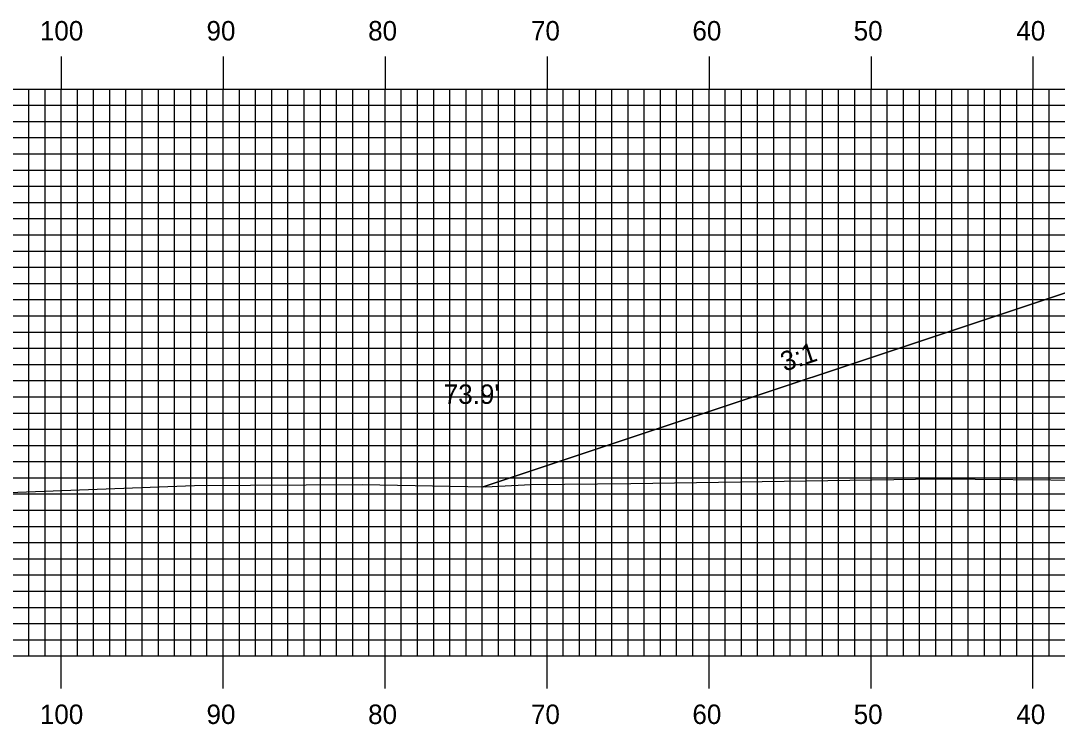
# Model space of a CAD drawing. Extents: x 1788943 to 1789287, y 442591 to 442811.
# Drawn here: x 1789006.7 to 1789070.7, y 442659.4 to 442702.9 of the extents above; entities that cross this region are included whole.
import ezdxf

# ---------------------------------------------------------------- set-up
doc = ezdxf.new("R2010")
doc.units = 0
for name, color, linetype in [('ANNOTATION', 7, 'Continuous'), ('D_Roadway_Centerline', 7, 'Continuous'), ('D_Roadway_SlopeLines', 7, 'Continuous'), ('D_Text_Standard', 7, 'Continuous'), ('H_V ANNOTATION', 7, 'Continuous'), ('MAJOR', 7, 'Continuous'), ('MINOR', 7, 'Continuous'), ('S_Roadway_Centerline', 7, 'Continuous')]:
    doc.layers.add(name, color=color, linetype=linetype)

msp = doc.modelspace()

# ---------------------------------------------------------------- linework, layer by layer
at = {"layer": 'D_Roadway_Centerline'}
msp.add_lwpolyline([(1789035.212, 442674.103), (1789075.728, 442687.608), (1789079.49, 442688.548), (1789087.728, 442690.608), (1789097.156, 442690.985), (1789109.156, 442691.249), (1789121.156, 442691.513), (1789137.57, 442690.857), (1789145.201, 442688.949), (1789149.57, 442687.857), (1789185.572, 442675.856)], dxfattribs=at)
at = {"layer": 'D_Roadway_SlopeLines'}
msp.add_lwpolyline([(1789087.728, 442690.608), (1789075.728, 442687.608), (1789035.212, 442674.103)], dxfattribs=at)
at = {"layer": 'MAJOR'}
for p, q in [((1789009.156, 442700.669), (1789009.156, 442698.665)), ((1789019.156, 442700.669), (1789019.156, 442698.665)), ((1789029.156, 442700.669), (1789029.156, 442698.665)), ((1789039.156, 442700.669), (1789039.156, 442698.665)), ((1789049.156, 442700.669), (1789049.156, 442698.665)), ((1789059.156, 442700.669), (1789059.156, 442698.665)), ((1789069.156, 442700.669), (1789069.156, 442698.665)), ((1788969.156, 442698.665), (1789249.156, 442698.665)), ((1788969.156, 442698.665), (1789249.156, 442698.665)), ((1789009.156, 442663.665), (1789009.156, 442698.665)), ((1789019.156, 442663.665), (1789019.156, 442698.665)), ((1789029.156, 442663.665), (1789029.156, 442698.665)), ((1789039.156, 442663.665), (1789039.156, 442698.665)), ((1789049.156, 442663.665), (1789049.156, 442698.665)), ((1789059.156, 442663.665), (1789059.156, 442698.665)), ((1789069.156, 442663.665), (1789069.156, 442698.665)), ((1788969.156, 442693.665), (1789249.156, 442693.665)), ((1788969.156, 442688.665), (1789249.156, 442688.665)), ((1788969.156, 442683.665), (1789249.156, 442683.665)), ((1788969.156, 442678.665), (1789249.156, 442678.665)), ((1788969.156, 442673.665), (1789249.156, 442673.665)), ((1788969.156, 442668.665), (1789249.156, 442668.665)), ((1788969.156, 442663.665), (1789249.156, 442663.665)), ((1788969.156, 442663.665), (1789249.156, 442663.665)), ((1789009.156, 442661.661), (1789009.156, 442663.665)), ((1789019.156, 442661.661), (1789019.156, 442663.665)), ((1789029.156, 442661.661), (1789029.156, 442663.665)), ((1789039.156, 442661.661), (1789039.156, 442663.665)), ((1789049.156, 442661.661), (1789049.156, 442663.665)), ((1789059.156, 442661.661), (1789059.156, 442663.665)), ((1789069.156, 442661.661), (1789069.156, 442663.665))]:
    msp.add_line(p, q, dxfattribs=at)
at = {"layer": 'MINOR'}
for p, q in [((1789007.156, 442663.665), (1789007.156, 442698.665)), ((1789008.156, 442663.665), (1789008.156, 442698.665)), ((1789010.156, 442663.665), (1789010.156, 442698.665)), ((1789011.156, 442663.665), (1789011.156, 442698.665)), ((1789012.156, 442663.665), (1789012.156, 442698.665)), ((1789013.156, 442663.665), (1789013.156, 442698.665)), ((1789014.156, 442663.665), (1789014.156, 442698.665)), ((1789015.156, 442663.665), (1789015.156, 442698.665)), ((1789016.156, 442663.665), (1789016.156, 442698.665)), ((1789017.156, 442663.665), (1789017.156, 442698.665)), ((1789018.156, 442663.665), (1789018.156, 442698.665)), ((1789020.156, 442663.665), (1789020.156, 442698.665)), ((1789021.156, 442663.665), (1789021.156, 442698.665)), ((1789022.156, 442663.665), (1789022.156, 442698.665)), ((1789023.156, 442663.665), (1789023.156, 442698.665)), ((1789024.156, 442663.665), (1789024.156, 442698.665)), ((1789025.156, 442663.665), (1789025.156, 442698.665)), ((1789026.156, 442663.665), (1789026.156, 442698.665)), ((1789027.156, 442663.665), (1789027.156, 442698.665)), ((1789028.156, 442663.665), (1789028.156, 442698.665)), ((1789030.156, 442663.665), (1789030.156, 442698.665)), ((1789031.156, 442663.665), (1789031.156, 442698.665)), ((1789032.156, 442663.665), (1789032.156, 442698.665)), ((1789033.156, 442663.665), (1789033.156, 442698.665)), ((1789034.156, 442663.665), (1789034.156, 442698.665)), ((1789035.156, 442663.665), (1789035.156, 442698.665)), ((1789036.156, 442663.665), (1789036.156, 442698.665)), ((1789037.156, 442663.665), (1789037.156, 442698.665)), ((1789038.156, 442663.665), (1789038.156, 442698.665)), ((1789040.156, 442663.665), (1789040.156, 442698.665)), ((1789041.156, 442663.665), (1789041.156, 442698.665)), ((1789042.156, 442663.665), (1789042.156, 442698.665)), ((1789043.156, 442663.665), (1789043.156, 442698.665)), ((1789044.156, 442663.665), (1789044.156, 442698.665)), ((1789045.156, 442663.665), (1789045.156, 442698.665)), ((1789046.156, 442663.665), (1789046.156, 442698.665)), ((1789047.156, 442663.665), (1789047.156, 442698.665)), ((1789048.156, 442663.665), (1789048.156, 442698.665)), ((1789050.156, 442663.665), (1789050.156, 442698.665)), ((1789051.156, 442663.665), (1789051.156, 442698.665)), ((1789052.156, 442663.665), (1789052.156, 442698.665)), ((1789053.156, 442663.665), (1789053.156, 442698.665)), ((1789054.156, 442663.665), (1789054.156, 442698.665)), ((1789055.156, 442663.665), (1789055.156, 442698.665)), ((1789056.156, 442663.665), (1789056.156, 442698.665)), ((1789057.156, 442663.665), (1789057.156, 442698.665)), ((1789058.156, 442663.665), (1789058.156, 442698.665)), ((1789060.156, 442663.665), (1789060.156, 442698.665)), ((1789061.156, 442663.665), (1789061.156, 442698.665)), ((1789062.156, 442663.665), (1789062.156, 442698.665)), ((1789063.156, 442663.665), (1789063.156, 442698.665)), ((1789064.156, 442663.665), (1789064.156, 442698.665)), ((1789065.156, 442663.665), (1789065.156, 442698.665)), ((1789066.156, 442663.665), (1789066.156, 442698.665)), ((1789067.156, 442663.665), (1789067.156, 442698.665)), ((1789068.156, 442663.665), (1789068.156, 442698.665)), ((1789070.156, 442663.665), (1789070.156, 442698.665)), ((1788969.156, 442697.665), (1789249.156, 442697.665)), ((1788969.156, 442696.665), (1789249.156, 442696.665)), ((1788969.156, 442695.665), (1789249.156, 442695.665)), ((1788969.156, 442694.665), (1789249.156, 442694.665)), ((1788969.156, 442692.665), (1789249.156, 442692.665)), ((1788969.156, 442691.665), (1789249.156, 442691.665)), ((1788969.156, 442690.665), (1789249.156, 442690.665)), ((1788969.156, 442689.665), (1789249.156, 442689.665)), ((1788969.156, 442687.665), (1789249.156, 442687.665)), ((1788969.156, 442686.665), (1789249.156, 442686.665)), ((1788969.156, 442685.665), (1789249.156, 442685.665)), ((1788969.156, 442684.665), (1789249.156, 442684.665)), ((1788969.156, 442682.665), (1789249.156, 442682.665)), ((1788969.156, 442681.665), (1789249.156, 442681.665)), ((1788969.156, 442680.665), (1789249.156, 442680.665)), ((1788969.156, 442679.665), (1789249.156, 442679.665)), ((1788969.156, 442677.665), (1789249.156, 442677.665)), ((1788969.156, 442676.665), (1789249.156, 442676.665)), ((1788969.156, 442675.665), (1789249.156, 442675.665)), ((1788969.156, 442674.665), (1789249.156, 442674.665)), ((1788969.156, 442672.665), (1789249.156, 442672.665)), ((1788969.156, 442671.665), (1789249.156, 442671.665)), ((1788969.156, 442670.665), (1789249.156, 442670.665)), ((1788969.156, 442669.665), (1789249.156, 442669.665)), ((1788969.156, 442667.665), (1789249.156, 442667.665)), ((1788969.156, 442666.665), (1789249.156, 442666.665)), ((1788969.156, 442665.665), (1789249.156, 442665.665)), ((1788969.156, 442664.665), (1789249.156, 442664.665))]:
    msp.add_line(p, q, dxfattribs=at)
at = {"layer": 'S_Roadway_Centerline'}
msp.add_lwpolyline([(1788969.156, 442673.126), (1788975.587, 442673.267), (1788980.337, 442673.282), (1788992.47, 442673.404), (1788999.284, 442673.444), (1789001.31, 442673.457), (1789005.912, 442673.766), (1789017.386, 442674.191), (1789027.741, 442674.248), (1789035.35, 442674.1), (1789038.181, 442674.242), (1789044.319, 442674.31), (1789063.262, 442674.604), (1789072.58, 442674.527)], dxfattribs=at)

# ---------------------------------------------------------------- texts
at = {"layer": 'ANNOTATION'}
msp.add_text('3:1', height=1.2, rotation=18.43478, dxfattribs=at).set_placement((1789053.809, 442681.21))
at = {"layer": 'D_Text_Standard'}
msp.add_text("73.9'", height=1.2, dxfattribs=at).set_placement((1789032.778, 442679.228))
at = {"layer": 'H_V ANNOTATION'}
for s, p in [('100', (1789007.84, 442701.665)), ('90', (1789018.129, 442701.665)), ('80', (1789028.107, 442701.665)), ('70', (1789038.161, 442701.665)), ('60', (1789048.129, 442701.665)), ('50', (1789058.086, 442701.665)), ('40', (1789068.129, 442701.665)), ('100', (1789007.84, 442659.465)), ('90', (1789018.129, 442659.465)), ('80', (1789028.107, 442659.465)), ('70', (1789038.161, 442659.465)), ('60', (1789048.129, 442659.465)), ('50', (1789058.086, 442659.465)), ('40', (1789068.129, 442659.465))]:
    msp.add_text(s, height=1.2, dxfattribs=at).set_placement(p)

doc.saveas('drawing.dxf')
